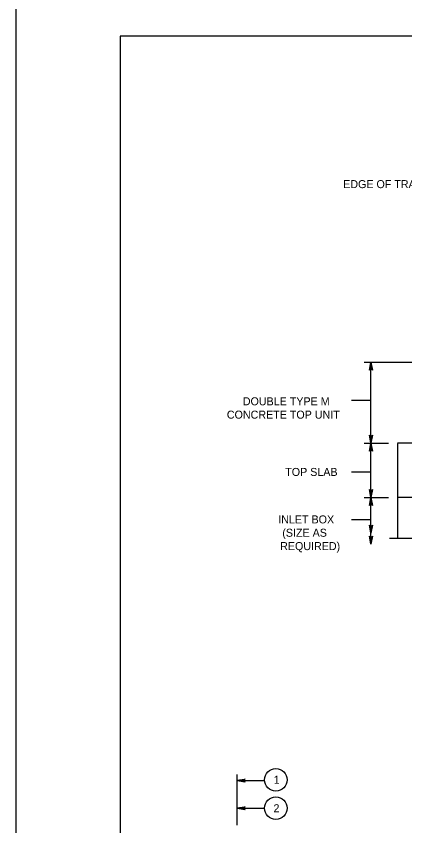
# Model space of a CAD drawing. Extents: x 2087776 to 2104538, y 970919 to 982612.
# Drawn here: x 2090535 to 2091013, y 973797 to 974792 of the extents above; entities that cross this region are included whole.
import ezdxf

# ---------------------------------------------------------------- set-up
doc = ezdxf.new("R2010")
doc.units = 0
doc.layers.add('1', color=7, linetype='Continuous')
doc.layers.add('PLT-BNDY', color=7, linetype='Continuous')

msp = doc.modelspace()

# ---------------------------------------------------------------- linework, layer by layer
at = {"layer": '1'}
for p, q in [((2090962.88, 974367.03), (2091045.3, 974367.03)), ((2090971.34, 974142.99), (2090971.34, 974367.03)), ((2090947.4, 974320.08), (2090971.34, 974320.08)), ((2090962.88, 974267.2), (2090992.76, 974267.2)), ((2091704, 974267.2), (2091004, 974267.2)), ((2091004, 974267.03), (2091004, 974150.53)), ((2090947.4, 974232.03), (2090971.34, 974232.03)), ((2090962.88, 974200.53), (2090992.76, 974200.53)), ((2091704, 974200.53), (2091004, 974200.53)), ((2090947.4, 974173.54), (2090971.34, 974173.54)), ((2090993.96, 974150.53), (2091025.65, 974150.53)), ((2090806.73, 973797.53), (2090806.73, 973860.08)), ((2090806.73, 973852.48), (2090840.4, 973852.48)), ((2090806.73, 973818.4), (2090840.37, 973818.4))]:
    msp.add_line(p, q, dxfattribs=at)
for points in [[(2093241.55, 972917.37), (2093241.55, 974767.76), (2090662.81, 974767.76), (2090662.81, 972917.37), (2093241.55, 972917.37), (2093241.55, 973003.85), (2092585.39, 973003.85), (2092585.39, 973216.04), (2093241.55, 973216.04), (2093241.55, 973311.07), (2092585.39, 973311.07), (2092585.39, 972917.37), (2092843.92, 972917.37), (2092843.92, 973003.85), (2092843.92, 972917.37), (2093096.55, 972917.37), (2093096.55, 973003.85), (2093096.55, 972963.44), (2093241.55, 972963.44)], [(2090971.34, 974367.03), (2090973.18, 974357.24), (2090972.92, 974357.62), (2090972.66, 974358), (2090972.33, 974358.19), (2090972, 974358.39), (2090971.67, 974358.44), (2090971.34, 974358.5), (2090971.01, 974358.44), (2090970.69, 974358.39), (2090970.36, 974358.19), (2090970.03, 974358), (2090969.77, 974357.62), (2090969.51, 974357.24), (2090971.34, 974367.03), (2090969.77, 974357.62), (2090970.03, 974358), (2090971.34, 974367.03), (2090970.36, 974358.19), (2090970.69, 974358.39), (2090971.34, 974367.03), (2090971.01, 974358.44), (2090971.34, 974358.5), (2090971.34, 974367.03), (2090971.67, 974358.44), (2090972, 974358.39), (2090971.34, 974367.03), (2090972.33, 974358.19), (2090972.66, 974358), (2090971.34, 974367.03), (2090972.92, 974357.62)], [(2090971.34, 974267.2), (2090969.51, 974276.98), (2090969.77, 974276.6), (2090970.03, 974276.23), (2090970.36, 974276.03), (2090970.69, 974275.84), (2090971.01, 974275.78), (2090971.34, 974275.73), (2090971.67, 974275.78), (2090972, 974275.84), (2090972.33, 974276.03), (2090972.66, 974276.23), (2090972.92, 974276.6), (2090973.18, 974276.98), (2090971.34, 974267.2), (2090972.92, 974276.6), (2090972.66, 974276.23), (2090971.34, 974267.2), (2090972.33, 974276.03), (2090972, 974275.84), (2090971.34, 974267.2), (2090971.67, 974275.78), (2090971.34, 974275.73), (2090971.34, 974267.2), (2090971.01, 974275.78), (2090970.69, 974275.84), (2090971.34, 974267.2), (2090970.36, 974276.03), (2090970.03, 974276.23), (2090971.34, 974267.2), (2090969.77, 974276.6)], [(2090971.34, 974267.2), (2090973.18, 974257.41), (2090972.92, 974257.79), (2090972.66, 974258.16), (2090972.33, 974258.36), (2090972, 974258.55), (2090971.67, 974258.61), (2090971.34, 974258.67), (2090971.01, 974258.61), (2090970.69, 974258.55), (2090970.36, 974258.36), (2090970.03, 974258.16), (2090969.77, 974257.79), (2090969.51, 974257.41), (2090971.34, 974267.2), (2090969.77, 974257.79), (2090970.03, 974258.16), (2090971.34, 974267.2), (2090970.36, 974258.36), (2090970.69, 974258.55), (2090971.34, 974267.2), (2090971.01, 974258.61), (2090971.34, 974258.67), (2090971.34, 974267.2), (2090971.67, 974258.61), (2090972, 974258.55), (2090971.34, 974267.2), (2090972.33, 974258.36), (2090972.66, 974258.16), (2090971.34, 974267.2), (2090972.92, 974257.79)], [(2090971.34, 974200.53), (2090969.51, 974210.31), (2090969.77, 974209.93), (2090970.03, 974209.56), (2090970.36, 974209.36), (2090970.69, 974209.17), (2090971.01, 974209.11), (2090971.34, 974209.06), (2090971.67, 974209.11), (2090972, 974209.17), (2090972.33, 974209.36), (2090972.66, 974209.56), (2090972.92, 974209.93), (2090973.18, 974210.31), (2090971.34, 974200.53), (2090972.92, 974209.93), (2090972.66, 974209.56), (2090971.34, 974200.53), (2090972.33, 974209.36), (2090972, 974209.17), (2090971.34, 974200.53), (2090971.67, 974209.11), (2090971.34, 974209.06), (2090971.34, 974200.53), (2090971.01, 974209.11), (2090970.69, 974209.17), (2090971.34, 974200.53), (2090970.36, 974209.36), (2090970.03, 974209.56), (2090971.34, 974200.53), (2090969.77, 974209.93)], [(2090971.34, 974200.53), (2090973.18, 974190.74), (2090972.92, 974191.12), (2090972.66, 974191.49), (2090972.33, 974191.69), (2090972, 974191.88), (2090971.67, 974191.94), (2090971.34, 974192), (2090971.01, 974191.94), (2090970.69, 974191.88), (2090970.36, 974191.69), (2090970.03, 974191.49), (2090969.77, 974191.12), (2090969.51, 974190.74), (2090971.34, 974200.53), (2090969.77, 974191.12), (2090970.03, 974191.49), (2090971.34, 974200.53), (2090970.36, 974191.69), (2090970.69, 974191.88), (2090971.34, 974200.53), (2090971.01, 974191.94), (2090971.34, 974192), (2090971.34, 974200.53), (2090971.67, 974191.94), (2090972, 974191.88), (2090971.34, 974200.53), (2090972.33, 974191.69), (2090972.66, 974191.49), (2090971.34, 974200.53), (2090972.92, 974191.12)], [(2090971.34, 974156.74), (2090969.51, 974166.53), (2090969.77, 974166.15), (2090970.03, 974165.77), (2090970.36, 974165.58), (2090970.69, 974165.38), (2090971.01, 974165.33), (2090971.34, 974165.27), (2090971.67, 974165.33), (2090972, 974165.38), (2090972.33, 974165.58), (2090972.66, 974165.77), (2090972.92, 974166.15), (2090973.18, 974166.53), (2090971.34, 974156.74), (2090972.92, 974166.15), (2090972.66, 974165.77), (2090971.34, 974156.74), (2090972.33, 974165.58), (2090972, 974165.38), (2090971.34, 974156.74), (2090971.67, 974165.33), (2090971.34, 974165.27), (2090971.34, 974156.74), (2090971.01, 974165.33), (2090970.69, 974165.38), (2090971.34, 974156.74), (2090970.36, 974165.58), (2090970.03, 974165.77), (2090971.34, 974156.74), (2090969.77, 974166.15)], [(2090971.34, 974142.99), (2090969.51, 974152.78), (2090969.77, 974152.4), (2090970.03, 974152.02), (2090970.36, 974151.83), (2090970.69, 974151.63), (2090971.01, 974151.58), (2090971.34, 974151.52), (2090971.67, 974151.58), (2090972, 974151.63), (2090972.33, 974151.83), (2090972.66, 974152.02), (2090972.92, 974152.4), (2090973.18, 974152.78), (2090971.34, 974142.99), (2090972.92, 974152.4), (2090972.66, 974152.02), (2090971.34, 974142.99), (2090972.33, 974151.83), (2090972, 974151.63), (2090971.34, 974142.99), (2090971.67, 974151.58), (2090971.34, 974151.52), (2090971.34, 974142.99), (2090971.01, 974151.58), (2090970.69, 974151.63), (2090971.34, 974142.99), (2090970.36, 974151.83), (2090970.03, 974152.02), (2090971.34, 974142.99), (2090969.77, 974152.4)], [(2090806.73, 973852.48), (2090816.52, 973854.31), (2090816.14, 973854.05), (2090815.76, 973853.79), (2090815.57, 973853.46), (2090815.38, 973853.13), (2090815.32, 973852.81), (2090815.26, 973852.48), (2090815.32, 973852.15), (2090815.38, 973851.82), (2090815.57, 973851.49), (2090815.76, 973851.17), (2090816.14, 973850.9), (2090816.52, 973850.64), (2090806.73, 973852.48), (2090816.14, 973850.9), (2090815.76, 973851.17), (2090806.73, 973852.48), (2090815.57, 973851.49), (2090815.38, 973851.82), (2090806.73, 973852.48), (2090815.32, 973852.15), (2090815.26, 973852.48), (2090806.73, 973852.48), (2090815.32, 973852.81), (2090815.38, 973853.13), (2090806.73, 973852.48), (2090815.57, 973853.46), (2090815.76, 973853.79), (2090806.73, 973852.48), (2090816.14, 973854.05)], [(2090806.73, 973818.4), (2090816.52, 973820.23), (2090816.14, 973819.97), (2090815.76, 973819.71), (2090815.57, 973819.38), (2090815.38, 973819.06), (2090815.32, 973818.73), (2090815.26, 973818.4), (2090815.32, 973818.07), (2090815.38, 973817.74), (2090815.57, 973817.42), (2090815.76, 973817.09), (2090816.14, 973816.83), (2090816.52, 973816.57), (2090806.73, 973818.4), (2090816.14, 973816.83), (2090815.76, 973817.09), (2090806.73, 973818.4), (2090815.57, 973817.42), (2090815.38, 973817.74), (2090806.73, 973818.4), (2090815.32, 973818.07), (2090815.26, 973818.4), (2090806.73, 973818.4), (2090815.32, 973818.73), (2090815.38, 973819.06), (2090806.73, 973818.4), (2090815.57, 973819.38), (2090815.76, 973819.71), (2090806.73, 973818.4), (2090816.14, 973819.97)]]:
    msp.add_lwpolyline(points, dxfattribs=at)
for centre in [(2090854.25, 973853.41), (2090854.25, 973818.4)]:
    msp.add_circle(centre, 13.89, dxfattribs=at)
at = {"layer": 'PLT-BNDY'}
msp.add_lwpolyline([(2090534.86, 974816.97), (2093294.05, 974816.97), (2093294.05, 972868.16), (2090534.86, 972868.16)], close=True, dxfattribs=at)

# ---------------------------------------------------------------- texts
at = {"layer": '1'}
for s, height, p in [('EDGE OF TRAVEL LANE', 9.8425, (2090937.19, 974580.94)), ('DOUBLE TYPE M', 9.8425, (2090813.7, 974313.88)), ('CONCRETE TOP UNIT', 9.8425, (2090794.05, 974297.48)), ('TOP SLAB', 9.843, (2090865.89, 974227.03)), ('INLET BOX', 9.843, (2090857.29, 974168.64)), ('(SIZE AS', 9.843, (2090862.29, 974152.24)), ('REQUIRED)', 9.843, (2090859.62, 974135.84)), ('1', 9.84, (2090851.7, 973848.49)), ('2', 9.84, (2090851.46, 973813.48))]:
    msp.add_text(s, height=height, dxfattribs=at).set_placement(p)

doc.saveas('drawing.dxf')
